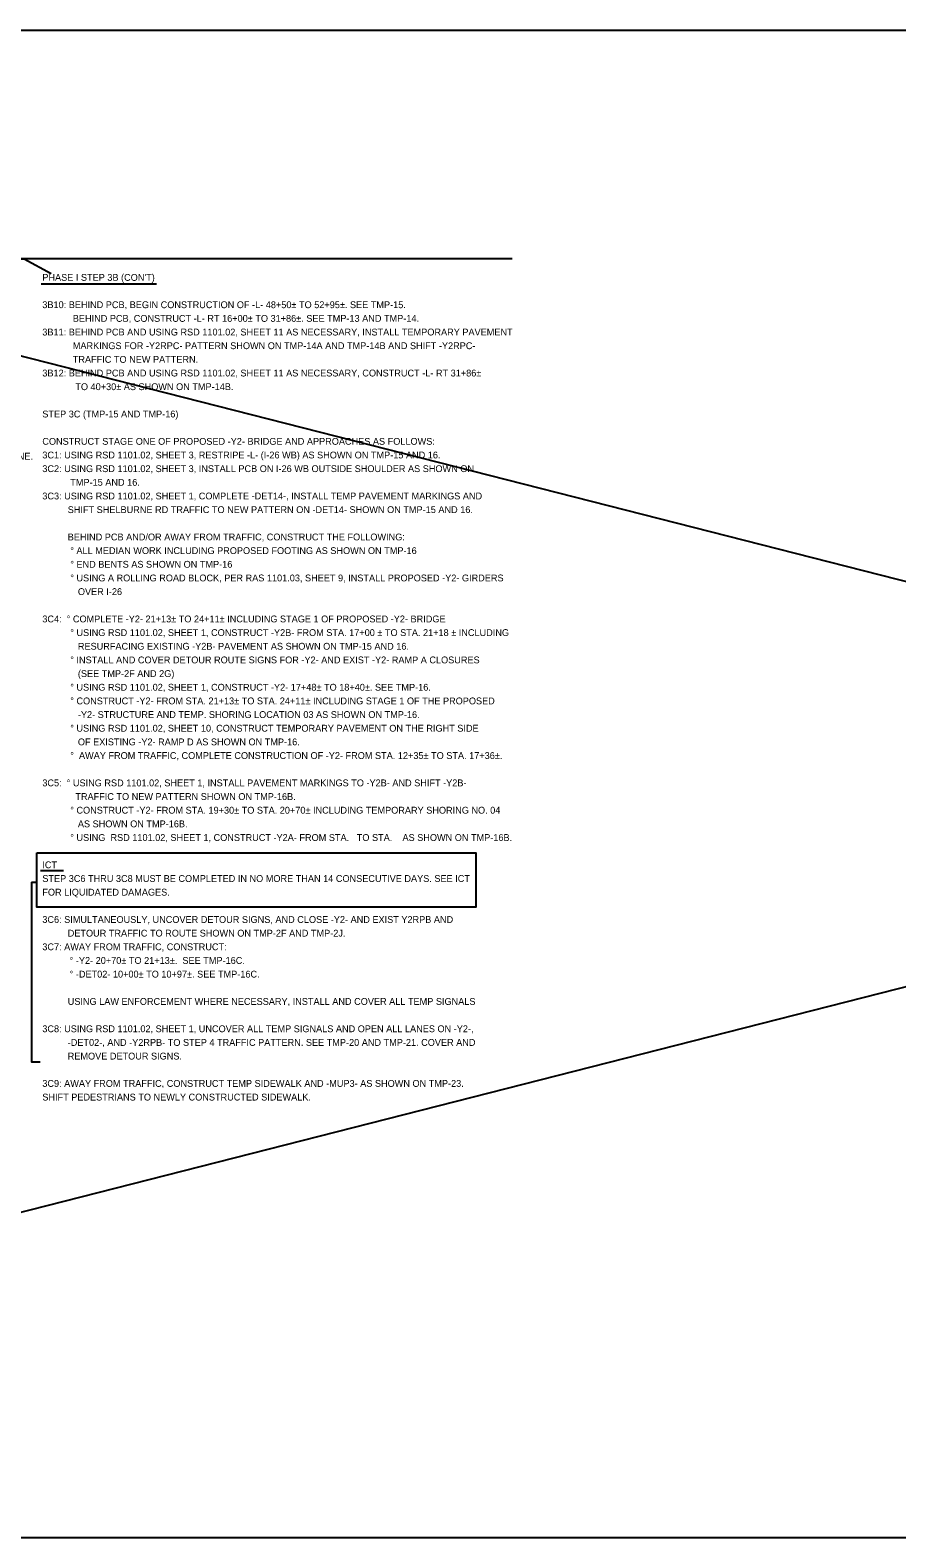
# Model space of a CAD drawing. Extents: x 2483905 to 2494512, y 366160 to 372330.
# Drawn here: x 2488018 to 2488905, y 368441 to 369986 of the extents above; entities that cross this region are included whole.
import ezdxf

# ---------------------------------------------------------------- set-up
doc = ezdxf.new("R2010")
doc.units = 0
for name, color, linetype in [('Scratch_Level_4', 7, 'Continuous'), ('Scratch_Level_6', 7, 'Continuous'), ('TC SHEET BORDER LINE THIN', 7, 'Continuous')]:
    doc.layers.add(name, color=color, linetype=linetype)

msp = doc.modelspace()

# ---------------------------------------------------------------- linework, layer by layer
at = {"layer": 'Scratch_Level_4'}
for p, q in [((2486701.2, 368441.1), (2492754.6, 369986.2)), ((2486701.2, 369986.2), (2492754.6, 368441.1))]:
    msp.add_line(p, q, dxfattribs=at)
msp.add_lwpolyline([(2486701.2, 369986.2), (2492754.6, 369986.2), (2492754.6, 368441.1), (2486701.2, 368441.1)], close=True, dxfattribs=at)
at = {"layer": 'Scratch_Level_6'}
msp.add_lwpolyline([(2487011.6, 369751.7), (2487039.5, 369736.7), (2487511.6, 369751.7), (2487539.5, 369736.7), (2488011.6, 369751.7), (2488039.5, 369736.7)], dxfattribs=at)
at = {"layer": 'TC SHEET BORDER LINE THIN'}
for p, q in [((2488511.6, 369751.7), (2487011.6, 369751.7)), ((2488029.2, 369726.1), (2488147.3, 369726.1)), ((2488028.5, 369124.9), (2488052.1, 369124.9)), ((2488019.3, 369112.9), (2488024.7, 369112.9))]:
    msp.add_line(p, q, dxfattribs=at)
msp.add_lwpolyline([(2488024.7, 369143.1), (2488474.2, 369143.1), (2488474.2, 369087.5), (2488024.7, 369087.5)], close=True, dxfattribs=at)
msp.add_lwpolyline([(2488019.3, 369112.9), (2488019.3, 368928.8), (2488028.2, 368928.8)], dxfattribs=at)

# ---------------------------------------------------------------- texts
for s, p in [("PHASE I STEP 3B (CON'T)", (2488030.3, 369729.3)), ('3B10: BEHIND PCB, BEGIN CONSTRUCTION OF -L- 48+50± TO 52+95±. SEE TMP-15.', (2488030.3, 369701.3)), ('            BEHIND PCB, CONSTRUCT -L- RT 16+00± TO 31+86±. SEE TMP-13 AND TMP-14.', (2488030.3, 369687.3)), ('3B11: BEHIND PCB AND USING RSD 1101.02, SHEET 11 AS NECESSARY, INSTALL TEMPORARY PAVEMENT', (2488030.3, 369673.3)), ('            MARKINGS FOR -Y2RPC- PATTERN SHOWN ON TMP-14A AND TMP-14B AND SHIFT -Y2RPC- ', (2488030.3, 369659.3)), ('            TRAFFIC TO NEW PATTERN.', (2488030.3, 369645.3)), ('3B12: BEHIND PCB AND USING RSD 1101.02, SHEET 11 AS NECESSARY, CONSTRUCT -L- RT 31+86± ', (2488030.3, 369631.3)), ('             TO 40+30± AS SHOWN ON TMP-14B.', (2488030.3, 369617.3)), ('STEP 3C (TMP-15 AND TMP-16)', (2488030.3, 369589.3)), ('CONSTRUCT STAGE ONE OF PROPOSED -Y2- BRIDGE AND APPROACHES AS FOLLOWS:', (2488030.3, 369561.3)), ('       TWO-LANE, TWO-WAY TRAFFIC USING INCIDENTAL STONE TO COVER UP THE INSTALLED WATER LINE.', (2487529.8, 369546.1)), ('3C1: USING RSD 1101.02, SHEET 3, RESTRIPE -L- (I-26 WB) AS SHOWN ON TMP-15 AND 16.', (2488030.3, 369547.3)), ('3C2: USING RSD 1101.02, SHEET 3, INSTALL PCB ON I-26 WB OUTSIDE SHOULDER AS SHOWN ON ', (2488030.3, 369533.3)), ('           TMP-15 AND 16.', (2488030.3, 369519.3)), ('3C3: USING RSD 1101.02, SHEET 1, COMPLETE -DET14-, INSTALL TEMP PAVEMENT MARKINGS AND ', (2488030.3, 369505.3)), ('          SHIFT SHELBURNE RD TRAFFIC TO NEW PATTERN ON -DET14- SHOWN ON TMP-15 AND 16.', (2488030.3, 369491.3)), ('          BEHIND PCB AND/OR AWAY FROM TRAFFIC, CONSTRUCT THE FOLLOWING:', (2488030.3, 369463.3)), ('           ° ALL MEDIAN WORK INCLUDING PROPOSED FOOTING AS SHOWN ON TMP-16', (2488030.3, 369449.3)), ('           ° END BENTS AS SHOWN ON TMP-16', (2488030.3, 369435.3)), ('           ° USING A ROLLING ROAD BLOCK, PER RAS 1101.03, SHEET 9, INSTALL PROPOSED -Y2- GIRDERS ', (2488030.3, 369421.3)), ('              OVER I-26', (2488030.3, 369407.3)), ('3C4:  ° COMPLETE -Y2- 21+13± TO 24+11± INCLUDING STAGE 1 OF PROPOSED -Y2- BRIDGE', (2488030.3, 369379.3)), ('           ° USING RSD 1101.02, SHEET 1, CONSTRUCT -Y2B- FROM STA. 17+00 ± TO STA. 21+18 ± INCLUDING', (2488030.3, 369365.3)), ('              RESURFACING EXISTING -Y2B- PAVEMENT AS SHOWN ON TMP-15 AND 16.', (2488030.3, 369351.3)), ('           ° INSTALL AND COVER DETOUR ROUTE SIGNS FOR -Y2- AND EXIST -Y2- RAMP A CLOSURES', (2488030.3, 369337.3)), ('              (SEE TMP-2F AND 2G)', (2488030.3, 369323.3)), ('           ° USING RSD 1101.02, SHEET 1, CONSTRUCT -Y2- 17+48± TO 18+40±. SEE TMP-16.', (2488030.3, 369309.3)), ('           ° CONSTRUCT -Y2- FROM STA. 21+13± TO STA. 24+11± INCLUDING STAGE 1 OF THE PROPOSED', (2488030.3, 369295.3)), ('              -Y2- STRUCTURE AND TEMP. SHORING LOCATION 03 AS SHOWN ON TMP-16.', (2488030.3, 369281.3)), ('           ° USING RSD 1101.02, SHEET 10, CONSTRUCT TEMPORARY PAVEMENT ON THE RIGHT SIDE', (2488030.3, 369267.3)), ('              OF EXISTING -Y2- RAMP D AS SHOWN ON TMP-16.', (2488030.3, 369253.3)), ('           °  AWAY FROM TRAFFIC, COMPLETE CONSTRUCTION OF -Y2- FROM STA. 12+35± TO STA. 17+36±.', (2488030.3, 369239.3)), ('3C5:  ° USING RSD 1101.02, SHEET 1, INSTALL PAVEMENT MARKINGS TO -Y2B- AND SHIFT -Y2B-', (2488030.3, 369211.3)), ('             TRAFFIC TO NEW PATTERN SHOWN ON TMP-16B.', (2488030.3, 369197.3)), ('           ° CONSTRUCT -Y2- FROM STA. 19+30± TO STA. 20+70± INCLUDING TEMPORARY SHORING NO. 04 ', (2488030.3, 369183.3)), ('              AS SHOWN ON TMP-16B.', (2488030.3, 369169.3)), ('           ° USING  RSD 1101.02, SHEET 1, CONSTRUCT -Y2A- FROM STA.   TO STA.    AS SHOWN ON TMP-16B.    ', (2488030.3, 369155.3)), ('ICT', (2488030.3, 369127.3)), ('STEP 3C6 THRU 3C8 MUST BE COMPLETED IN NO MORE THAN 14 CONSECUTIVE DAYS. SEE ICT', (2488030.3, 369113.3)), ('FOR LIQUIDATED DAMAGES.', (2488030.3, 369099.3)), ('3C6: SIMULTANEOUSLY, UNCOVER DETOUR SIGNS, AND CLOSE -Y2- AND EXIST Y2RPB AND', (2488030.3, 369071.3)), ('          DETOUR TRAFFIC TO ROUTE SHOWN ON TMP-2F AND TMP-2J.  ', (2488030.3, 369057.3)), ('3C7: AWAY FROM TRAFFIC, CONSTRUCT:', (2488030.3, 369043.3)), ('° -Y2- 20+70± TO 21+13±.  SEE TMP-16C.', (2488058.3, 369029.3)), ('° -DET02- 10+00± TO 10+97±. SEE TMP-16C.', (2488058.3, 369015.3)), ('          USING LAW ENFORCEMENT WHERE NECESSARY, INSTALL AND COVER ALL TEMP SIGNALS', (2488030.3, 368987.3)), ('3C8: USING RSD 1101.02, SHEET 1, UNCOVER ALL TEMP SIGNALS AND OPEN ALL LANES ON -Y2-,', (2488030.3, 368959.3)), ('          -DET02-, AND -Y2RPB- TO STEP 4 TRAFFIC PATTERN. SEE TMP-20 AND TMP-21. COVER AND ', (2488030.3, 368945.3)), ('          REMOVE DETOUR SIGNS.', (2488030.3, 368931.3)), ('3C9: AWAY FROM TRAFFIC, CONSTRUCT TEMP SIDEWALK AND -MUP3- AS SHOWN ON TMP-23.', (2488030.3, 368903.3)), ('SHIFT PEDESTRIANS TO NEWLY CONSTRUCTED SIDEWALK.', (2488030.3, 368889.3))]:
    msp.add_text(s, height=7, dxfattribs=at).set_placement(p)

doc.saveas('drawing.dxf')
